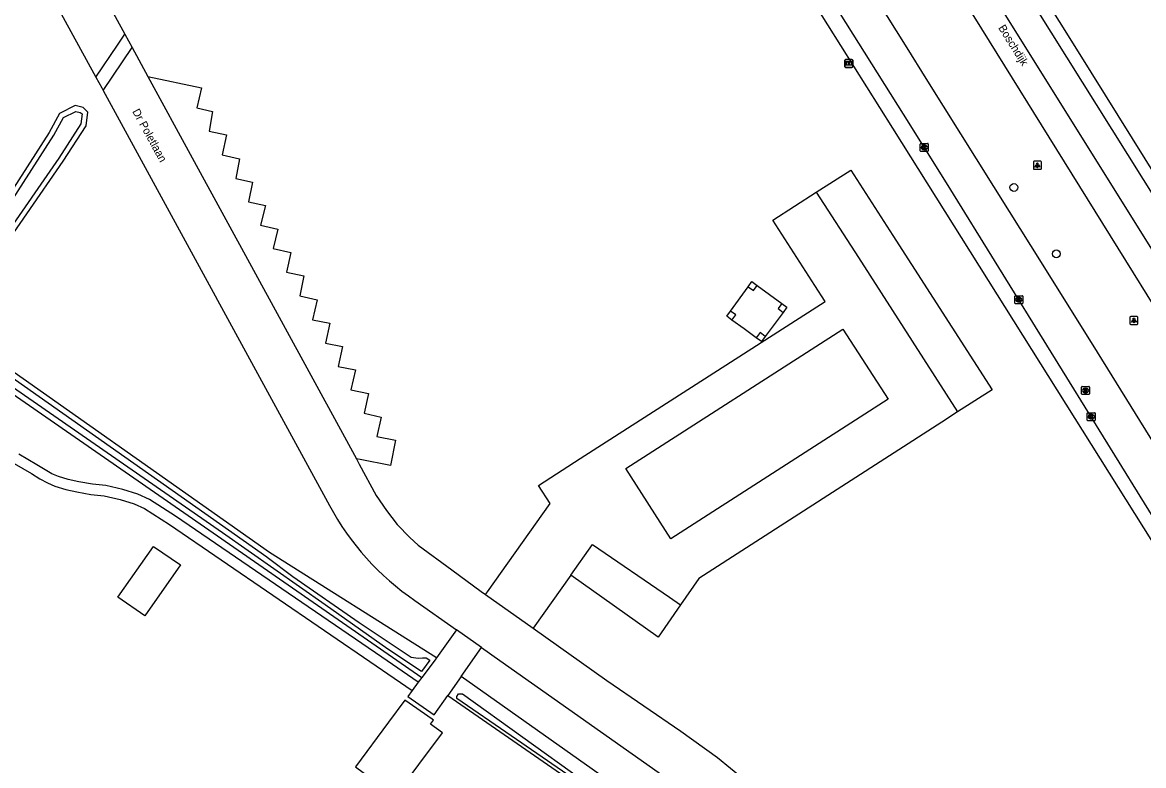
# Model space of a CAD drawing. Extents: x 158132 to 159658, y 385257 to 387209.
# Drawn here: x 159226.8 to 159366.9, y 386283.7 to 386376.6 of the extents above; entities that cross this region are included whole.
import ezdxf

# ---------------------------------------------------------------- set-up
doc = ezdxf.new("R2010")
doc.units = 0
for name, color, linetype in [('IMGEO_Boom', 7, 'Continuous'), ('IMGEO_Groenvoorziening', 7, 'Continuous'), ('IMGEO_Hoogspanningsmast', 7, 'Continuous'), ('IMGEO_Informatiebord', 7, 'Continuous'), ('IMGEO_Kolk', 7, 'Continuous'), ('IMGEO_Lichtpunt', 7, 'Continuous'), ('IMGEO_Loofbos', 7, 'Continuous'), ('IMGEO_Openbare_ruimte_label', 7, 'Continuous'), ('IMGEO_Pand', 7, 'Continuous'), ('IMGEO_Parkeervlak_halfverhard', 7, 'Continuous'), ('IMGEO_Parkeervlak_open', 7, 'Continuous'), ('IMGEO_Rijbaan_lokaal_gesloten', 7, 'Continuous'), ('IMGEO_Rijbaan_lokaal_open', 7, 'Continuous'), ('IMGEO_Rijbaan_regionaal_gesloten', 7, 'Continuous'), ('IMGEO_Rioolput', 7, 'Continuous'), ('IMGEO_Voetpad_gesloten', 7, 'Continuous'), ('IMGEO_Voetpad_onverhard', 7, 'Continuous'), ('IMGEO_Voetpad_open', 7, 'Continuous'), ('IMGEO_Waterloop', 7, 'Continuous')]:
    doc.layers.add(name, color=color, linetype=linetype)

msp = doc.modelspace()

# ---------------------------------------------------------------- linework, layer by layer
at = {"layer": 'IMGEO_Boom'}
for centre in [(159350.67, 386355.98), (159355.97, 386347.69)]:
    msp.add_circle(centre, 0.489, dxfattribs=at)
at = {"layer": 'IMGEO_Groenvoorziening'}
for points in [[(159218.25, 386339.52), (159231.93, 386359.27), (159234.77, 386363.69), (159234.98, 386365.4), (159234.4, 386365.97), (159233.42, 386366.2), (159231.48, 386365.22), (159230.18, 386362.85), (159214.68, 386338.75)], [(159278.55, 386297.2), (159257.71, 386310.39), (159218.55, 386337.95)], [(159217.06, 386312.22), (159213.29, 386318.85), (159216.49, 386323.83), (159216.86, 386324.34), (159218, 386325.9), (159221.92, 386331.29), (159222.6, 386331.73), (159223.48, 386331.64), (159276.73, 386294.75)], [(159279.96, 386292.51), (159317.86, 386266.27), (159320.25, 386264.54), (159322.4, 386262.12), (159329.77, 386251.87), (159330.22, 386251.29), (159330.82, 386251.14), (159331.31, 386251.49), (159332.05, 386252.03), (159332.3, 386252.55), (159324.83, 386262.89), (159322.11, 386265.69), (159318.79, 386268.6), (159281.64, 386294.89)]]:
    msp.add_lwpolyline(points, dxfattribs=at)
at = {"layer": 'IMGEO_Hoogspanningsmast'}
for points in [[(159317.48, 386343.57), (159317.95, 386344.22), (159318.6, 386343.74)], [(159317.48, 386343.57), (159318.13, 386343.1), (159318.6, 386343.74)], [(159315.46, 386339.42), (159314.81, 386339.9), (159315.28, 386340.54)], [(159315.46, 386339.42), (159315.93, 386340.07), (159315.28, 386340.54)], [(159321.68, 386341.48), (159321.21, 386340.84), (159321.85, 386340.37)], [(159321.68, 386341.48), (159322.33, 386341.01), (159321.85, 386340.37)], [(159319.61, 386337.36), (159318.97, 386337.84), (159318.49, 386337.19)], [(159319.61, 386337.36), (159319.13, 386336.72), (159318.49, 386337.19)]]:
    msp.add_lwpolyline(points, dxfattribs=at)
at = {"layer": 'IMGEO_Informatiebord'}
for p, q in [((159329.56, 386371.07), (159329.56, 386371.87)), ((159329.56, 386371.87), (159329.56, 386371.07)), ((159329.66, 386371.97), (159330.45, 386371.97)), ((159330.45, 386371.97), (159329.66, 386371.97)), ((159330.45, 386370.97), (159329.66, 386370.97)), ((159329.66, 386370.97), (159330.45, 386370.97)), ((159330.55, 386371.87), (159330.55, 386371.07)), ((159330.55, 386371.07), (159330.55, 386371.87))]:
    msp.add_line(p, q, dxfattribs=at)
for points in [[(159329.66, 386371.7), (159330.45, 386371.7), (159330.45, 386371.24), (159329.66, 386371.24), (159329.66, 386371.7)], [(159329.73, 386371.64), (159329.73, 386371.3), (159330, 386371.3), (159330, 386371.52), (159330.11, 386371.52), (159330.11, 386371.3), (159330.38, 386371.3), (159330.38, 386371.64), (159330.11, 386371.64), (159330.11, 386371.56), (159330, 386371.56), (159330, 386371.64), (159329.73, 386371.64)]]:
    msp.add_lwpolyline(points, dxfattribs=at)
for centre, start, end in [((159329.66, 386371.87), 90, 180), ((159329.66, 386371.87), 90, 180), ((159329.66, 386371.07), 180, 270), ((159329.66, 386371.07), 180, 270), ((159330.45, 386371.87), 0, 90), ((159330.45, 386371.87), 360, 90), ((159330.45, 386371.07), 270, 0), ((159330.45, 386371.07), 270, 0)]:
    msp.add_arc(centre, 0.1, start, end, dxfattribs=at)
at = {"layer": 'IMGEO_Kolk'}
for p, q in [((159338.98, 386360.56), (159338.98, 386361.41)), ((159339.05, 386361.48), (159339.91, 386361.48)), ((159339.47, 386361.26), (159339.49, 386361.26)), ((159339.98, 386361.41), (159339.98, 386360.56)), ((159339.91, 386360.48), (159339.05, 386360.48)), ((159339.49, 386360.7), (159339.47, 386360.7)), ((159350.79, 386341.53), (159350.79, 386342.39)), ((159350.86, 386342.46), (159351.72, 386342.46)), ((159351.28, 386342.24), (159351.3, 386342.24)), ((159351.3, 386341.68), (159351.28, 386341.68)), ((159351.79, 386342.39), (159351.79, 386341.53)), ((159351.72, 386341.46), (159350.86, 386341.46)), ((159359.84, 386326.91), (159359.84, 386327.76)), ((159359.91, 386327.84), (159360.76, 386327.84)), ((159360.32, 386327.62), (159360.35, 386327.62)), ((159360.84, 386327.76), (159360.84, 386326.91)), ((159360.76, 386326.84), (159359.91, 386326.84)), ((159360.35, 386327.06), (159360.32, 386327.06))]:
    msp.add_line(p, q, dxfattribs=at)
for points in [[(159338.98, 386360.56), (159338.98, 386361.41)], [(159339.05, 386361.48), (159339.91, 386361.48)], [(159339.3, 386361.18), (159339.42, 386361.18), (159339.42, 386361.03), (159339.55, 386361.18), (159339.72, 386361.18), (159339.57, 386361.03), (159339.72, 386360.78), (159339.57, 386360.78), (159339.49, 386360.95), (159339.42, 386360.88), (159339.42, 386360.78), (159339.3, 386360.78), (159339.3, 386361.18)], [(159339.98, 386361.41), (159339.98, 386360.56)], [(159339.91, 386360.48), (159339.05, 386360.48)], [(159350.79, 386341.53), (159350.79, 386342.39)], [(159350.86, 386342.46), (159351.72, 386342.46)], [(159351.11, 386342.16), (159351.23, 386342.16), (159351.23, 386342.01), (159351.36, 386342.16), (159351.53, 386342.16), (159351.38, 386342.01), (159351.53, 386341.76), (159351.38, 386341.76), (159351.3, 386341.92), (159351.23, 386341.86), (159351.23, 386341.76), (159351.11, 386341.76), (159351.11, 386342.16)], [(159351.79, 386342.39), (159351.79, 386341.53)], [(159351.72, 386341.46), (159350.86, 386341.46)], [(159359.84, 386326.91), (159359.84, 386327.76)], [(159359.91, 386327.84), (159360.76, 386327.84)], [(159360.84, 386327.76), (159360.84, 386326.91)], [(159360.76, 386326.84), (159359.91, 386326.84)], [(159360.16, 386327.54), (159360.28, 386327.54), (159360.28, 386327.39), (159360.41, 386327.54), (159360.57, 386327.54), (159360.43, 386327.39), (159360.58, 386327.14), (159360.43, 386327.14), (159360.34, 386327.3), (159360.28, 386327.24), (159360.28, 386327.14), (159360.16, 386327.14), (159360.16, 386327.54)]]:
    msp.add_lwpolyline(points, dxfattribs=at)
for centre, start, end in [((159339.06, 386361.41), 91.552, 178.448), ((159339.06, 386361.41), 91.552, 178.448), ((159339.9, 386361.41), 1.552, 88.448), ((159339.9, 386361.41), 1.552, 88.448), ((159339.06, 386360.56), 181.552, 268.448), ((159339.06, 386360.56), 181.552, 268.448), ((159339.9, 386360.56), 271.552, 358.448), ((159339.9, 386360.56), 271.552, 358.448), ((159350.87, 386342.38), 91.552, 178.448), ((159350.87, 386342.38), 91.552, 178.448), ((159351.71, 386342.38), 1.552, 88.448), ((159351.71, 386342.38), 1.552, 88.448), ((159350.87, 386341.54), 181.552, 268.448), ((159350.87, 386341.54), 181.552, 268.448), ((159351.71, 386341.54), 271.552, 358.448), ((159351.71, 386341.54), 271.552, 358.448), ((159359.91, 386327.76), 91.552, 178.448), ((159359.91, 386327.76), 91.552, 178.448), ((159360.76, 386327.76), 1.552, 88.448), ((159360.76, 386327.76), 1.552, 88.448), ((159359.91, 386326.91), 181.552, 268.448), ((159359.91, 386326.91), 181.552, 268.448), ((159360.76, 386326.91), 271.552, 358.448), ((159360.76, 386326.91), 271.552, 358.448)]:
    msp.add_arc(centre, 0.0765, start, end, dxfattribs=at)
for centre, major_axis, ratio, start_param, end_param in [((159339.47, 386360.98), (-0.387, 0.002), 0.722429, 4.712389, 7.853982), ((159339.49, 386360.98), (-0.39, 0.002), 0.717154, 1.570796, 4.712389), ((159351.28, 386341.96), (-0.387, 0.002), 0.722429, 4.712389, 7.853982), ((159351.3, 386341.96), (-0.39, 0.002), 0.717154, 1.570796, 4.712389), ((159360.32, 386327.34), (-0.387, 0.002), 0.722429, 4.712389, 7.853982), ((159360.35, 386327.34), (-0.39, 0.002), 0.717154, 1.570796, 4.712389)]:
    msp.add_ellipse(centre, major_axis=major_axis, ratio=ratio, start_param=start_param, end_param=end_param, dxfattribs=at)
at = {"layer": 'IMGEO_Lichtpunt'}
for p, q in [((159353.11, 386359.15), (159353.11, 386358.35)), ((159353.11, 386359.15), (159353.11, 386358.35)), ((159354.02, 386359.25), (159353.21, 386359.25)), ((159354.02, 386359.25), (159353.21, 386359.25)), ((159354.11, 386358.35), (159354.11, 386359.15)), ((159354.11, 386358.35), (159354.11, 386359.15)), ((159353.21, 386358.25), (159354.02, 386358.25)), ((159353.21, 386358.25), (159354.02, 386358.25)), ((159365.16, 386339.77), (159365.16, 386338.96)), ((159365.16, 386339.77), (159365.16, 386338.96)), ((159366.06, 386339.86), (159365.26, 386339.86)), ((159366.06, 386339.86), (159365.26, 386339.86)), ((159365.26, 386338.87), (159366.06, 386338.87)), ((159365.26, 386338.87), (159366.06, 386338.87)), ((159366.16, 386338.96), (159366.16, 386339.77)), ((159366.16, 386338.96), (159366.16, 386339.77))]:
    msp.add_line(p, q, dxfattribs=at)
for points in [[(159353.49, 386358.82), (159353.53, 386358.79), (159353.34, 386358.53), (159353.3, 386358.55), (159353.49, 386358.82)], [(159353.59, 386358.77), (159353.64, 386358.77), (159353.64, 386358.45), (159353.59, 386358.45), (159353.59, 386358.77)], [(159353.7, 386358.79), (159353.74, 386358.82), (159353.92, 386358.55), (159353.89, 386358.53), (159353.7, 386358.79)], [(159365.54, 386339.43), (159365.57, 386339.41), (159365.39, 386339.14), (159365.35, 386339.17), (159365.54, 386339.43)], [(159365.64, 386339.39), (159365.68, 386339.39), (159365.68, 386339.06), (159365.64, 386339.06), (159365.64, 386339.39)], [(159365.75, 386339.41), (159365.79, 386339.43), (159365.97, 386339.17), (159365.93, 386339.14), (159365.75, 386339.41)]]:
    msp.add_lwpolyline(points, dxfattribs=at)
for centre in [(159353.61, 386358.95), (159365.66, 386339.57)]:
    msp.add_circle(centre, 0.0994, dxfattribs=at)
for centre, start, end in [((159353.21, 386359.15), 90, 180), ((159353.21, 386359.15), 90, 180), ((159354.02, 386359.15), 0, 90), ((159354.02, 386359.15), 0, 90), ((159353.21, 386358.35), 180, 270), ((159353.21, 386358.35), 180, 270), ((159354.02, 386358.35), 270, 0), ((159354.02, 386358.35), 270, 360), ((159365.26, 386339.77), 90, 180), ((159365.26, 386339.77), 90, 180), ((159365.26, 386338.96), 180, 270), ((159365.26, 386338.96), 180, 270), ((159366.06, 386339.77), 0, 90), ((159366.06, 386339.77), 0, 90), ((159366.06, 386338.96), 270, 0), ((159366.06, 386338.96), 270, 360)]:
    msp.add_arc(centre, 0.0946, start, end, dxfattribs=at)
at = {"layer": 'IMGEO_Loofbos'}
for points in [[(159315.28, 386340.54), (159317.48, 386343.57)], [(159318.6, 386343.74), (159320.15, 386342.61), (159321.68, 386341.48)], [(159321.85, 386340.37), (159319.61, 386337.36)], [(159318.49, 386337.19), (159316.97, 386338.31), (159315.46, 386339.42)]]:
    msp.add_lwpolyline(points, dxfattribs=at)
at = {"layer": 'IMGEO_Pand'}
msp.add_lwpolyline([(159242.11, 386302.47), (159238.75, 386304.81), (159243.2, 386311.13), (159246.59, 386308.83), (159242.11, 386302.47)], dxfattribs=at)
at = {"layer": 'IMGEO_Parkeervlak_halfverhard'}
for points in [[(159325.99, 386355.4), (159330.29, 386358.16), (159335.55, 386349.97), (159347.95, 386330.69), (159343.65, 386327.93)], [(159309.03, 386303.82), (159306.25, 386299.78), (159295.31, 386307.53)]]:
    msp.add_lwpolyline(points, dxfattribs=at)
at = {"layer": 'IMGEO_Parkeervlak_open'}
msp.add_lwpolyline([(159242.49, 386369.86), (159249.21, 386368.41), (159248.6, 386365.92), (159250.58, 386365.48), (159250.15, 386363.02), (159252.34, 386362.56), (159251.77, 386360.05), (159253.96, 386359.57), (159253.48, 386357.11), (159255.55, 386356.65), (159255.05, 386354.18), (159257.18, 386353.74), (159256.57, 386351.26), (159258.74, 386350.79), (159258.14, 386348.37), (159260.37, 386347.87), (159259.8, 386345.38), (159261.99, 386344.92), (159261.49, 386342.42), (159263.63, 386341.95), (159263.08, 386339.46), (159265.24, 386339.03), (159264.67, 386336.54), (159266.82, 386336.1), (159266.25, 386333.63), (159268.42, 386333.2), (159267.85, 386330.7), (159270.05, 386330.23), (159269.5, 386327.77), (159271.64, 386327.3), (159271.08, 386324.87), (159273.43, 386324.42), (159272.81, 386321.25), (159269.03, 386321.98), (159268.54, 386322.08)], dxfattribs=at)
at = {"layer": 'IMGEO_Rijbaan_lokaal_gesloten'}
for points in [[(159236.91, 386368.1), (159240.53, 386373.46)], [(159240.53, 386373.46), (159242.49, 386369.86)], [(159242.49, 386369.86), (159248.05, 386359.68), (159266.54, 386325.76), (159268.54, 386322.08)], [(159236.91, 386368.1), (159265.18, 386316.25)], [(159268.54, 386322.08), (159268.89, 386321.42), (159271.02, 386317.48), (159272.32, 386315.61), (159273.62, 386313.88), (159275.21, 386312.26), (159276.27, 386311.29), (159280.48, 386308.19), (159284.12, 386305.51), (159284.69, 386305.11)], [(159275.86, 386304.38), (159281.04, 386300.72)], [(159284.69, 386305.11), (159290.62, 386300.9)], [(159284.19, 386298.5), (159281.04, 386300.72)], [(159290.62, 386300.9), (159299.81, 386294.4), (159309.07, 386288.04), (159313.63, 386284.75), (159316.89, 386282.11), (159322.85, 386276.82), (159326.94, 386272.97), (159331.8, 386266.93), (159344.48, 386248.29), (159344.67, 386247.98), (159347.95, 386242.83)], [(159284.19, 386298.5), (159286.46, 386296.89), (159311.59, 386279.14), (159316.33, 386275.1), (159320.31, 386271.57), (159326.13, 386266.11)]]:
    msp.add_lwpolyline(points, dxfattribs=at)
msp.add_arc((159294.59, 386331.97), 33.35, 208.1365, 235.8374, dxfattribs=at)
at = {"layer": 'IMGEO_Rijbaan_lokaal_open'}
for points in [[(159368.42, 386314.26), (159342.27, 386356.54), (159336.87, 386365.14), (159318.51, 386394.36), (159300.96, 386422.44), (159295.37, 386431.39), (159272.54, 386467.97), (159257.46, 386492.38)], [(159392.53, 386284.71), (159360.58, 386336.26), (159352.77, 386348.74), (159350.12, 386352.97), (159339.93, 386369.27), (159337.12, 386373.76), (159316.19, 386407.15), (159305.08, 386424.92), (159298.35, 386435.69), (159274.93, 386473.31)], [(159226.65, 386398.61), (159227.16, 386397.82), (159227.72, 386396.87), (159228.26, 386395.92), (159228.78, 386394.95), (159239.61, 386375.13)], [(159223.26, 386393), (159236, 386369.77)], [(159236, 386369.77), (159238.69, 386373.76), (159239.61, 386375.13)], [(159239.61, 386375.13), (159240.53, 386373.46)], [(159236, 386369.77), (159236.74, 386368.41), (159236.91, 386368.1)], [(159284.69, 386305.11), (159284.94, 386305.47), (159292.74, 386316.48), (159291.29, 386318.74), (159296.51, 386322.1), (159327.09, 386341.75), (159325.82, 386343.72), (159320.56, 386351.91), (159325.99, 386355.4)], [(159325.99, 386355.4), (159331.26, 386347.21), (159343.65, 386327.93)], [(159307.83, 386312.1), (159302.2, 386320.86), (159329.32, 386338.29), (159334.95, 386329.53), (159307.83, 386312.1)], [(159343.65, 386327.93), (159341.68, 386326.66), (159311.31, 386307.14), (159309.03, 386303.82)], [(159295.31, 386307.53), (159298.04, 386311.37), (159307.64, 386304.78), (159309.03, 386303.82)], [(159295.31, 386307.53), (159290.62, 386300.9)]]:
    msp.add_lwpolyline(points, dxfattribs=at)
at = {"layer": 'IMGEO_Rijbaan_regionaal_gesloten'}
for points in [[(159342.02, 386399.64), (159351.36, 386384.68), (159358.7, 386372.92), (159383.7, 386332.81), (159412.25, 386287.13), (159435.45, 386250), (159469.32, 386195.75), (159500, 386146.68), (159500.71, 386145.54), (159504.21, 386139.91)], [(159340.68, 386398.8), (159350.35, 386383.31), (159351.38, 386381.66), (159384.22, 386329.19), (159418.21, 386274.6), (159433.62, 386250), (159457.5, 386211.88), (159499.59, 386144.35), (159500, 386143.69), (159502.82, 386139.09)], [(159499.65, 386137.22), (159464.48, 386193.71), (159376.24, 386334.94), (159348.02, 386380.17), (159337.59, 386396.88)], [(159496.38, 386135.29), (159490.64, 386144.47), (159476.21, 386167.57), (159463.53, 386187.91), (159450.9, 386207.96), (159427.26, 386246.56), (159425.1, 386250), (159405.9, 386280.49), (159387.21, 386310.53), (159345.73, 386377.33), (159334.62, 386395.01)]]:
    msp.add_lwpolyline(points, dxfattribs=at)
at = {"layer": 'IMGEO_Rioolput'}
for p, q in [((159359.12, 386330.19), (159359.12, 386331.04)), ((159359.19, 386331.11), (159360.05, 386331.11)), ((159359.61, 386330.89), (159359.63, 386330.89)), ((159360.12, 386331.04), (159360.12, 386330.19)), ((159360.05, 386330.11), (159359.19, 386330.11)), ((159359.63, 386330.33), (159359.6, 386330.33))]:
    msp.add_line(p, q, dxfattribs=at)
for points in [[(159359.12, 386330.19), (159359.12, 386331.04)], [(159359.19, 386331.11), (159360.05, 386331.11)], [(159359.71, 386330.81), (159359.46, 386330.81), (159359.46, 386330.41)], [(159359.46, 386330.41), (159359.58, 386330.41), (159359.58, 386330.58), (159359.59, 386330.58)], [(159359.63, 386330.73), (159359.58, 386330.73), (159359.58, 386330.65)], [(159359.58, 386330.65), (159359.63, 386330.65)], [(159359.64, 386330.55), (159359.71, 386330.41), (159359.85, 386330.41), (159359.78, 386330.54)], [(159360.12, 386331.04), (159360.12, 386330.19)], [(159360.05, 386330.11), (159359.19, 386330.11)]]:
    msp.add_lwpolyline(points, dxfattribs=at)
for centre, radius, start, end in [((159359.2, 386331.04), 0.0765, 91.552, 178.448), ((159359.2, 386331.04), 0.0765, 91.552, 178.448), ((159359.59, 386330.52), 0.0533, 26.0293, 88.6989), ((159359.64, 386330.64), 0.0964, 77.0061, 93.1865), ((159359.62, 386330.84), 0.19, 274.7715, 282.9687), ((159359.65, 386330.69), 0.0378, 276.6634, 79.6772), ((159359.71, 386330.7), 0.109, 350.3612, 89.416), ((159359.71, 386330.7), 0.112, 277.5842, 350.9817), ((159359.69, 386330.49), 0.108, 29.5134, 73.7905), ((159360.04, 386331.04), 0.0765, 1.552, 88.448), ((159360.04, 386331.04), 0.0765, 1.552, 88.448), ((159359.2, 386330.19), 0.0765, 181.552, 268.448), ((159359.2, 386330.19), 0.0765, 181.552, 268.448), ((159360.04, 386330.19), 0.0765, 271.552, 358.448), ((159360.04, 386330.19), 0.0765, 271.552, 358.448)]:
    msp.add_arc(centre, radius, start, end, dxfattribs=at)
for centre, major_axis, ratio, start_param, end_param in [((159359.61, 386330.61), (-0.387, 0.002), 0.722429, 4.712389, 7.853982), ((159359.63, 386330.61), (-0.39, 0.002), 0.717154, 1.570796, 4.712389)]:
    msp.add_ellipse(centre, major_axis=major_axis, ratio=ratio, start_param=start_param, end_param=end_param, dxfattribs=at)
at = {"layer": 'IMGEO_Voetpad_gesloten'}
for points in [[(159281.04, 386300.72), (159278.55, 386297.2)], [(159281.64, 386294.89), (159284.19, 386298.5)], [(159278.55, 386297.2), (159278.49, 386297.12), (159276.73, 386294.75)], [(159276.28, 386294.16), (159275.51, 386293.13)], [(159276.73, 386294.75), (159276.28, 386294.16)], [(159281.64, 386294.89), (159279.96, 386292.51)], [(159275.51, 386293.13), (159274.96, 386292.39), (159278.24, 386290.07), (159279.96, 386292.51)], [(159273.37, 386279.91), (159279.28, 386287.84), (159277.8, 386288.94), (159278.17, 386289.44), (159278.01, 386289.56), (159274.61, 386291.91), (159272.55, 386289.16), (159268.42, 386283.61), (159273.37, 386279.91)]]:
    msp.add_lwpolyline(points, dxfattribs=at)
at = {"layer": 'IMGEO_Voetpad_onverhard'}
for points in [[(159276.28, 386294.16), (159271.72, 386297.28), (159245.93, 386314.93), (159242.7, 386317), (159241.26, 386317.65), (159239.37, 386318.25), (159237.23, 386318.73), (159235.57, 386318.9), (159233.89, 386319.21), (159232.56, 386319.5), (159231.32, 386319.88), (159230.51, 386320.22), (159229.65, 386320.7), (159228.63, 386321.33), (159226.38, 386322.65)], [(159225.79, 386321.51), (159227.97, 386320.23), (159229, 386319.59), (159229.95, 386319.06), (159230.89, 386318.67), (159232.24, 386318.25), (159233.64, 386317.95), (159235.39, 386317.62), (159237.02, 386317.46), (159239.03, 386317.01), (159240.8, 386316.44), (159242.08, 386315.87), (159245.22, 386313.85), (159271, 386296.22), (159275.51, 386293.13)]]:
    msp.add_lwpolyline(points, dxfattribs=at)
at = {"layer": 'IMGEO_Voetpad_open'}
msp.add_lwpolyline([(159565.37, 385995.91), (159562.79, 386000), (159562.61, 386000.29), (159500, 386100.31), (159430.86, 386210.85), (159406.37, 386250), (159377.74, 386296.22), (159335.56, 386363.38), (159320.93, 386386.67), (159299.26, 386421.42), (159282.86, 386447.72), (159281.62, 386449.7), (159261.29, 386482.19), (159255.64, 386491.24)], dxfattribs=at)
at = {"layer": 'IMGEO_Waterloop'}
for points in [[(159215.25, 386338.38), (159230.75, 386362.51), (159231.97, 386364.71), (159233.51, 386365.49), (159234.06, 386365.36), (159234.27, 386365.16), (159234.12, 386363.92), (159231.37, 386359.65), (159217.69, 386339.9)], [(159218.16, 386337.4), (159257.34, 386309.83), (159257.4, 386309.79), (159260.6, 386307.38), (159268.91, 386301.61), (159275.39, 386297.29), (159276.27, 386297.18), (159276.79, 386297.21), (159277.27, 386297.21), (159277.7, 386296.91), (159276.69, 386295.5), (159272.49, 386298.29), (159264.66, 386303.83), (159251.8, 386312.83)], [(159251.8, 386312.83), (159223.5, 386332.44)], [(159304.57, 386275.96), (159287.87, 386287.45), (159281.08, 386292.14), (159281.08, 386292.37), (159281.31, 386292.72), (159281.79, 386292.7), (159296.87, 386281.87)]]:
    msp.add_lwpolyline(points, dxfattribs=at)

# ---------------------------------------------------------------- texts
at = {"layer": 'IMGEO_Openbare_ruimte_label'}
for s, rotation, p in [('Boschdijk', 301.9265, (159348.68, 386375.93)), ('Dr Poletlaan', 298.6928, (159240.52, 386365.48))]:
    msp.add_text(s, height=1, rotation=rotation, dxfattribs=at).set_placement(p)

doc.saveas('drawing.dxf')
